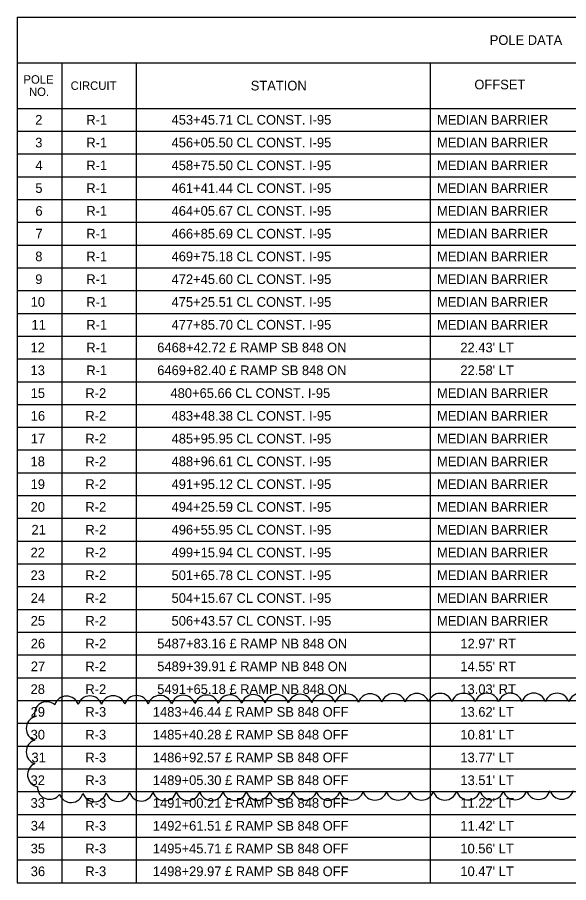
# Model space of a CAD drawing. Extents: x -816.7 to -800.7, y -2197.9 to -2187.9.
# Drawn here: x -816.04 to -812.04, y -2194.13 to -2187.86 of the extents above; entities that cross this region are included whole.
import ezdxf

# ---------------------------------------------------------------- set-up
doc = ezdxf.new("R2010")
doc.units = 0
for name, color, linetype in [('Cloud_dp', 7, 'Continuous'), ('SumBoxBorder_dp', 7, 'Continuous'), ('SumBoxLines_dp', 7, 'Continuous'), ('SumBoxLinesMin_dp', 7, 'Continuous'), ('TextLabel', 7, 'Continuous')]:
    doc.layers.add(name, color=color, linetype=linetype)

msp = doc.modelspace()

# ---------------------------------------------------------------- linework, layer by layer
at = {"layer": 'Cloud_dp'}
for centre, start, end in [((-815.6819, -2192.8631), 17.94937, 162.94937), ((-815.5126, -2192.8617), 17.94937, 162.94937), ((-815.3433, -2192.8604), 17.94937, 162.94937), ((-815.1741, -2192.8591), 17.94937, 162.94937), ((-815.0048, -2192.8577), 17.94937, 162.94937), ((-814.8355, -2192.8564), 17.94937, 162.94937), ((-814.6663, -2192.8551), 17.94937, 162.94937), ((-814.497, -2192.8538), 17.94937, 162.94937), ((-814.3277, -2192.8524), 17.94937, 162.94937), ((-814.1585, -2192.8511), 17.94937, 162.94937), ((-813.9892, -2192.8498), 17.94937, 162.94937), ((-813.8199, -2192.8485), 17.94104, 162.94104), ((-813.6507, -2192.8472), 17.91499, 162.91499), ((-813.4814, -2192.846), 17.8851, 162.8851), ((-813.3122, -2192.8449), 17.8509, 162.8509), ((-813.1429, -2192.844), 17.81126, 162.81126), ((-812.9737, -2192.8431), 17.76456, 162.76456), ((-812.8044, -2192.8424), 17.70842, 162.70842), ((-812.6352, -2192.8419), 17.63916, 162.63916), ((-812.4659, -2192.8416), 17.55068, 162.55068), ((-812.2967, -2192.8416), 17.43203, 162.43203), ((-812.1275, -2192.8421), 17.26077, 162.26077), ((-811.9584, -2192.8432), 16.98047, 161.98047), ((-815.8256, -2192.9035), 48.4646, 193.4646), ((-815.8852, -2193.0088), 107.5, 252.5), ((-815.8852, -2193.178), 107.5, 252.5), ((-815.8756, -2193.3437), 114.144, 259.144), ((-815.8036, -2193.4334), 178.34348, 323.34348), ((-815.6489, -2193.4564), 199.71315, 344.71315), ((-815.4792, -2193.4513), 198.75276, 343.75276), ((-815.3098, -2193.4482), 198.36843, 343.36843), ((-815.1404, -2193.4459), 198.14491, 343.14491), ((-814.9711, -2193.4442), 197.99402, 342.99402), ((-814.8018, -2193.4429), 197.8833, 342.8833), ((-814.6325, -2193.4419), 197.79757, 342.79757), ((-814.4632, -2193.4412), 197.72865, 342.72865), ((-814.2939, -2193.4406), 197.67166, 342.67166), ((-814.1246, -2193.4401), 197.62352, 342.62352), ((-813.9553, -2193.4398), 197.58216, 342.58216), ((-813.786, -2193.4396), 197.5461, 342.5461), ((-813.6167, -2193.4395), 197.51433, 342.51433), ((-813.4474, -2193.4395), 197.52177, 342.52177), ((-813.2782, -2193.4394), 197.56792, 342.56792), ((-813.1089, -2193.4391), 197.6205, 342.6205), ((-812.9397, -2193.4386), 197.68115, 342.68115), ((-812.7704, -2193.438), 197.75216, 342.75216), ((-812.6012, -2193.4371), 197.83689, 342.83689), ((-812.432, -2193.436), 197.94041, 342.94041), ((-812.2628, -2193.4345), 198.07089, 343.07089), ((-812.0936, -2193.4325), 198.24258, 343.24258)]:
    msp.add_arc(centre, 0.0887, start, end, dxfattribs=at)
at = {"layer": 'SumBoxBorder_dp'}
for p, q in [((-816.0386, -2187.8562), (-808.6136, -2187.8562)), ((-816.0386, -2187.8562), (-816.0386, -2194.1262)), ((-816.0386, -2188.1862), (-808.6136, -2188.1862)), ((-816.0386, -2188.1862), (-808.6136, -2188.1862)), ((-816.0386, -2194.1262), (-808.6136, -2194.1262))]:
    msp.add_line(p, q, dxfattribs=at)
at = {"layer": 'SumBoxLines_dp'}
for p, q in [((-815.7161, -2188.1862), (-815.7161, -2194.1262)), ((-815.7161, -2188.1862), (-815.7161, -2194.1262)), ((-815.1761, -2188.1862), (-815.1761, -2194.1262)), ((-815.1761, -2188.1862), (-815.1761, -2194.1262)), ((-813.0461, -2188.1862), (-813.0461, -2194.1262)), ((-813.0461, -2188.1862), (-813.0461, -2194.1262)), ((-816.0386, -2188.5162), (-808.6136, -2188.5162))]:
    msp.add_line(p, q, dxfattribs=at)
at = {"layer": 'SumBoxLinesMin_dp'}
for p, q in [((-816.0386, -2188.5162), (-808.6136, -2188.5162)), ((-816.0386, -2188.6812), (-808.6136, -2188.6812)), ((-816.0386, -2188.6812), (-808.6136, -2188.6812)), ((-816.0386, -2188.8462), (-808.6136, -2188.8462)), ((-816.0386, -2188.8462), (-808.6136, -2188.8462)), ((-816.0386, -2189.0112), (-808.6136, -2189.0112)), ((-816.0386, -2189.0112), (-808.6136, -2189.0112)), ((-816.0386, -2189.1762), (-808.6136, -2189.1762)), ((-816.0386, -2189.1762), (-808.6136, -2189.1762)), ((-816.0386, -2189.3412), (-808.6136, -2189.3412)), ((-816.0386, -2189.3412), (-808.6136, -2189.3412)), ((-816.0386, -2189.5062), (-808.6136, -2189.5062)), ((-816.0386, -2189.5062), (-808.6136, -2189.5062)), ((-816.0386, -2189.6712), (-808.6136, -2189.6712)), ((-816.0386, -2189.6712), (-808.6136, -2189.6712)), ((-816.0386, -2189.8362), (-808.6136, -2189.8362)), ((-816.0386, -2189.8362), (-808.6136, -2189.8362)), ((-816.0386, -2190.0012), (-808.6136, -2190.0012)), ((-816.0386, -2190.0012), (-808.6136, -2190.0012)), ((-816.0386, -2190.1662), (-808.6136, -2190.1662)), ((-816.0386, -2190.1662), (-808.6136, -2190.1662)), ((-816.0386, -2190.3312), (-808.6136, -2190.3312)), ((-816.0386, -2190.3312), (-808.6136, -2190.3312)), ((-816.0386, -2190.4962), (-808.6136, -2190.4962)), ((-816.0386, -2190.4962), (-808.6136, -2190.4962)), ((-816.0386, -2190.6612), (-808.6136, -2190.6612)), ((-816.0386, -2190.6612), (-808.6136, -2190.6612)), ((-816.0386, -2190.8262), (-808.6136, -2190.8262)), ((-816.0386, -2190.8262), (-808.6136, -2190.8262)), ((-816.0386, -2190.9912), (-808.6136, -2190.9912)), ((-816.0386, -2190.9912), (-808.6136, -2190.9912)), ((-816.0386, -2191.1562), (-808.6136, -2191.1562)), ((-816.0386, -2191.1562), (-808.6136, -2191.1562)), ((-816.0386, -2191.3212), (-808.6136, -2191.3212)), ((-816.0386, -2191.3212), (-808.6136, -2191.3212)), ((-816.0386, -2191.4862), (-808.6136, -2191.4862)), ((-816.0386, -2191.4862), (-808.6136, -2191.4862)), ((-816.0386, -2191.6512), (-808.6136, -2191.6512)), ((-816.0386, -2191.6512), (-808.6136, -2191.6512)), ((-816.0386, -2191.8162), (-808.6136, -2191.8162)), ((-816.0386, -2191.8162), (-808.6136, -2191.8162)), ((-816.0386, -2191.9812), (-808.6136, -2191.9812)), ((-816.0386, -2191.9812), (-808.6136, -2191.9812)), ((-816.0386, -2192.1462), (-808.6136, -2192.1462)), ((-816.0386, -2192.1462), (-808.6136, -2192.1462)), ((-816.0386, -2192.3112), (-808.6136, -2192.3112)), ((-816.0386, -2192.3112), (-808.6136, -2192.3112)), ((-816.0386, -2192.4762), (-809.8961, -2192.4762)), ((-816.0386, -2192.4762), (-808.6136, -2192.4762)), ((-816.0386, -2192.6412), (-808.6136, -2192.6412)), ((-816.0386, -2192.6412), (-808.6136, -2192.6412)), ((-816.0386, -2192.8062), (-808.6136, -2192.8062)), ((-816.0386, -2192.8062), (-808.6136, -2192.8062)), ((-816.0386, -2192.9712), (-808.6136, -2192.9712)), ((-816.0386, -2192.9712), (-808.6136, -2192.9712)), ((-816.0386, -2193.1362), (-808.6136, -2193.1362)), ((-816.0386, -2193.1362), (-808.6136, -2193.1362)), ((-816.0386, -2193.3012), (-808.6136, -2193.3012)), ((-816.0386, -2193.3012), (-808.6136, -2193.3012)), ((-816.0386, -2193.4662), (-808.6136, -2193.4662)), ((-816.0386, -2193.4662), (-808.6136, -2193.4662)), ((-816.0386, -2193.6312), (-808.6136, -2193.6312)), ((-816.0386, -2193.6312), (-808.6136, -2193.6312)), ((-816.0386, -2193.7962), (-808.6136, -2193.7962)), ((-816.0386, -2193.7962), (-808.6136, -2193.7962)), ((-816.0386, -2193.9612), (-808.6136, -2193.9612)), ((-816.0386, -2193.9612), (-808.6136, -2193.9612))]:
    msp.add_line(p, q, dxfattribs=at)

# ---------------------------------------------------------------- texts
at = {"layer": 'TextLabel'}
for s, height, p in [('POLE DATA', 0.07, (-812.615, -2188.0562)), ('POLE', 0.06125, (-815.994, -2188.3372)), ('CIRCUIT', 0.06125, (-815.652, -2188.3818)), ('STATION', 0.07, (-814.3469, -2188.3862)), ('OFFSET', 0.07, (-812.7263, -2188.3782)), ('NO.', 0.06125, (-815.954, -2188.4265)), ('2', 0.07, (-815.9087, -2188.6337)), ('R-1', 0.07, (-815.5385, -2188.6337)), ('453+45.71 CL CONST. I-95', 0.07, (-814.9208, -2188.6337)), ('MEDIAN BARRIER', 0.07, (-812.9969, -2188.6337)), ('3', 0.07, (-815.9088, -2188.7987)), ('R-1', 0.07, (-815.5385, -2188.7987)), ('456+05.50 CL CONST. I-95', 0.07, (-814.9208, -2188.7987)), ('MEDIAN BARRIER', 0.07, (-812.9969, -2188.7987)), ('4', 0.07, (-815.9074, -2188.9637)), ('R-1', 0.07, (-815.5385, -2188.9637)), ('458+75.50 CL CONST. I-95', 0.07, (-814.9208, -2188.9637)), ('MEDIAN BARRIER', 0.07, (-812.9969, -2188.9637)), ('5', 0.07, (-815.9079, -2189.1287)), ('R-1', 0.07, (-815.5385, -2189.1287)), ('461+41.44 CL CONST. I-95', 0.07, (-814.9208, -2189.1287)), ('MEDIAN BARRIER', 0.07, (-812.9969, -2189.1287)), ('6', 0.07, (-815.9073, -2189.2937)), ('R-1', 0.07, (-815.5385, -2189.2937)), ('464+05.67 CL CONST. I-95', 0.07, (-814.9208, -2189.2937)), ('MEDIAN BARRIER', 0.07, (-812.9969, -2189.2937)), ('7', 0.07, (-815.9067, -2189.4587)), ('R-1', 0.07, (-815.5385, -2189.4587)), ('466+85.69 CL CONST. I-95', 0.07, (-814.9208, -2189.4587)), ('MEDIAN BARRIER', 0.07, (-812.9969, -2189.4587)), ('8', 0.07, (-815.9085, -2189.6237)), ('R-1', 0.07, (-815.5385, -2189.6237)), ('469+75.18 CL CONST. I-95', 0.07, (-814.9208, -2189.6237)), ('MEDIAN BARRIER', 0.07, (-812.9969, -2189.6237)), ('9', 0.07, (-815.9084, -2189.7887)), ('R-1', 0.07, (-815.5385, -2189.7887)), ('472+45.60 CL CONST. I-95', 0.07, (-814.9208, -2189.7887)), ('MEDIAN BARRIER', 0.07, (-812.9969, -2189.7887)), ('10', 0.07, (-815.942, -2189.9537)), ('R-1', 0.07, (-815.5385, -2189.9537)), ('475+25.51 CL CONST. I-95', 0.07, (-814.9208, -2189.9537)), ('MEDIAN BARRIER', 0.07, (-812.9969, -2189.9537)), ('477+85.70 CL CONST. I-95', 0.07, (-814.9208, -2190.1187)), ('11', 0.07, (-815.9359, -2190.1187)), ('R-1', 0.07, (-815.5385, -2190.1187)), ('MEDIAN BARRIER', 0.07, (-812.9969, -2190.1187)), ('12', 0.07, (-815.9426, -2190.2837)), ('R-1', 0.07, (-815.5385, -2190.2837)), ('6468+42.72 £ RAMP SB 848 ON', 0.07, (-815.0245, -2190.2837)), ("22.43' LT", 0.07, (-812.8279, -2190.2837)), ('13', 0.07, (-815.9426, -2190.4487)), ('R-1', 0.07, (-815.5385, -2190.4487)), ('6469+82.40 £ RAMP SB 848 ON', 0.07, (-815.0245, -2190.4487)), ("22.58' LT", 0.07, (-812.8279, -2190.4487)), ('15', 0.07, (-815.9417, -2190.6137)), ('R-2', 0.07, (-815.5452, -2190.6137)), (' 480+65.66 CL CONST. I-95', 0.07, (-814.9547, -2190.6137)), ('MEDIAN BARRIER', 0.07, (-812.9969, -2190.6137)), ('16', 0.07, (-815.9412, -2190.7787)), ('R-2', 0.07, (-815.5452, -2190.7787)), ('483+48.38 CL CONST. I-95', 0.07, (-814.9208, -2190.7787)), ('MEDIAN BARRIER', 0.07, (-812.9969, -2190.7787)), ('17', 0.07, (-815.9406, -2190.9437)), ('R-2', 0.07, (-815.5452, -2190.9437)), ('485+95.95 CL CONST. I-95', 0.07, (-814.9208, -2190.9437)), ('MEDIAN BARRIER', 0.07, (-812.9969, -2190.9437)), ('18', 0.07, (-815.9424, -2191.1087)), ('R-2', 0.07, (-815.5452, -2191.1087)), ('488+96.61 CL CONST. I-95', 0.07, (-814.9208, -2191.1087)), ('MEDIAN BARRIER', 0.07, (-812.9969, -2191.1087)), ('19', 0.07, (-815.9422, -2191.2737)), ('R-2', 0.07, (-815.5452, -2191.2737)), ('491+95.12 CL CONST. I-95', 0.07, (-814.9208, -2191.2737)), ('MEDIAN BARRIER', 0.07, (-812.9969, -2191.2737)), ('20', 0.07, (-815.942, -2191.4387)), ('R-2', 0.07, (-815.5452, -2191.4387)), ('494+25.59 CL CONST. I-95', 0.07, (-814.9208, -2191.4387)), ('MEDIAN BARRIER', 0.07, (-812.9969, -2191.4387)), ('21', 0.07, (-815.9359, -2191.6037)), ('R-2', 0.07, (-815.5452, -2191.6037)), ('496+55.95 CL CONST. I-95', 0.07, (-814.9208, -2191.6037)), ('MEDIAN BARRIER', 0.07, (-812.9969, -2191.6037)), ('22', 0.07, (-815.9426, -2191.7687)), ('R-2', 0.07, (-815.5452, -2191.7687)), ('499+15.94 CL CONST. I-95', 0.07, (-814.9208, -2191.7687)), ('MEDIAN BARRIER', 0.07, (-812.9969, -2191.7687)), ('23', 0.07, (-815.9426, -2191.9337)), ('R-2', 0.07, (-815.5452, -2191.9337)), ('501+65.78 CL CONST. I-95', 0.07, (-814.9208, -2191.9337)), ('MEDIAN BARRIER', 0.07, (-812.9969, -2191.9337)), ('24', 0.07, (-815.9412, -2192.0987)), ('R-2', 0.07, (-815.5452, -2192.0987)), ('504+15.67 CL CONST. I-95', 0.07, (-814.9208, -2192.0987)), ('MEDIAN BARRIER', 0.07, (-812.9969, -2192.0987)), ('25', 0.07, (-815.9417, -2192.2637)), ('R-2', 0.07, (-815.5452, -2192.2637)), ('506+43.57 CL CONST. I-95', 0.07, (-814.9208, -2192.2637)), ('MEDIAN BARRIER', 0.07, (-812.9969, -2192.2637)), ('26', 0.07, (-815.9412, -2192.4287)), ('R-2', 0.07, (-815.5452, -2192.4287)), ('5487+83.16 £ RAMP NB 848 ON', 0.07, (-815.0245, -2192.4287)), ("12.97' RT", 0.07, (-812.8279, -2192.4287)), ('27', 0.07, (-815.9406, -2192.5937)), ('R-2', 0.07, (-815.5452, -2192.5937)), ('5489+39.91 £ RAMP NB 848 ON', 0.07, (-815.0245, -2192.5937)), ("14.55' RT", 0.07, (-812.8279, -2192.5937)), ('28', 0.07, (-815.9424, -2192.7587)), ('R-2', 0.07, (-815.5452, -2192.7587)), ('5491+65.18 £ RAMP NB 848 ON', 0.07, (-815.0245, -2192.7587)), ("13.03' RT", 0.07, (-812.8279, -2192.7587)), ('29', 0.07, (-815.9422, -2192.9237)), ('R-3', 0.07, (-815.5453, -2192.9237)), ('1483+46.44 £ RAMP SB 848 OFF', 0.07, (-815.0564, -2192.9237)), ("13.62' LT", 0.07, (-812.8279, -2192.9237)), ('30', 0.07, (-815.942, -2193.0887)), ('R-3', 0.07, (-815.5453, -2193.0887)), ('1485+40.28 £ RAMP SB 848 OFF', 0.07, (-815.0564, -2193.0887)), ("10.81' LT", 0.07, (-812.8279, -2193.0887)), ('31', 0.07, (-815.9359, -2193.2537)), ('R-3', 0.07, (-815.5453, -2193.2537)), ('1486+92.57 £ RAMP SB 848 OFF', 0.07, (-815.0564, -2193.2537)), ("13.77' LT", 0.07, (-812.8279, -2193.2537)), ('32', 0.07, (-815.9426, -2193.4187)), ('R-3', 0.07, (-815.5453, -2193.4187)), ('1489+05.30 £ RAMP SB 848 OFF', 0.07, (-815.0564, -2193.4187)), ("13.51' LT", 0.07, (-812.8279, -2193.4187)), ('33', 0.07, (-815.9426, -2193.5837)), ('R-3', 0.07, (-815.5453, -2193.5837)), ('1491+00.21 £ RAMP SB 848 OFF', 0.07, (-815.0564, -2193.5837)), ("11.22' LT", 0.07, (-812.8279, -2193.5837)), ('34', 0.07, (-815.9412, -2193.7487)), ('R-3', 0.07, (-815.5453, -2193.7487)), ('1492+61.51 £ RAMP SB 848 OFF', 0.07, (-815.0564, -2193.7487)), ("11.42' LT", 0.07, (-812.8279, -2193.7487)), ('35', 0.07, (-815.9417, -2193.9137)), ('R-3', 0.07, (-815.5453, -2193.9137)), ('1495+45.71 £ RAMP SB 848 OFF', 0.07, (-815.0564, -2193.9137)), ("10.56' LT", 0.07, (-812.8279, -2193.9137)), ('36', 0.07, (-815.9412, -2194.0787)), ('R-3', 0.07, (-815.5453, -2194.0787)), ('1498+29.97 £ RAMP SB 848 OFF', 0.07, (-815.0564, -2194.0787)), ("10.47' LT", 0.07, (-812.8279, -2194.0787))]:
    msp.add_text(s, height=height, dxfattribs=at).set_placement(p)

doc.saveas('drawing.dxf')
